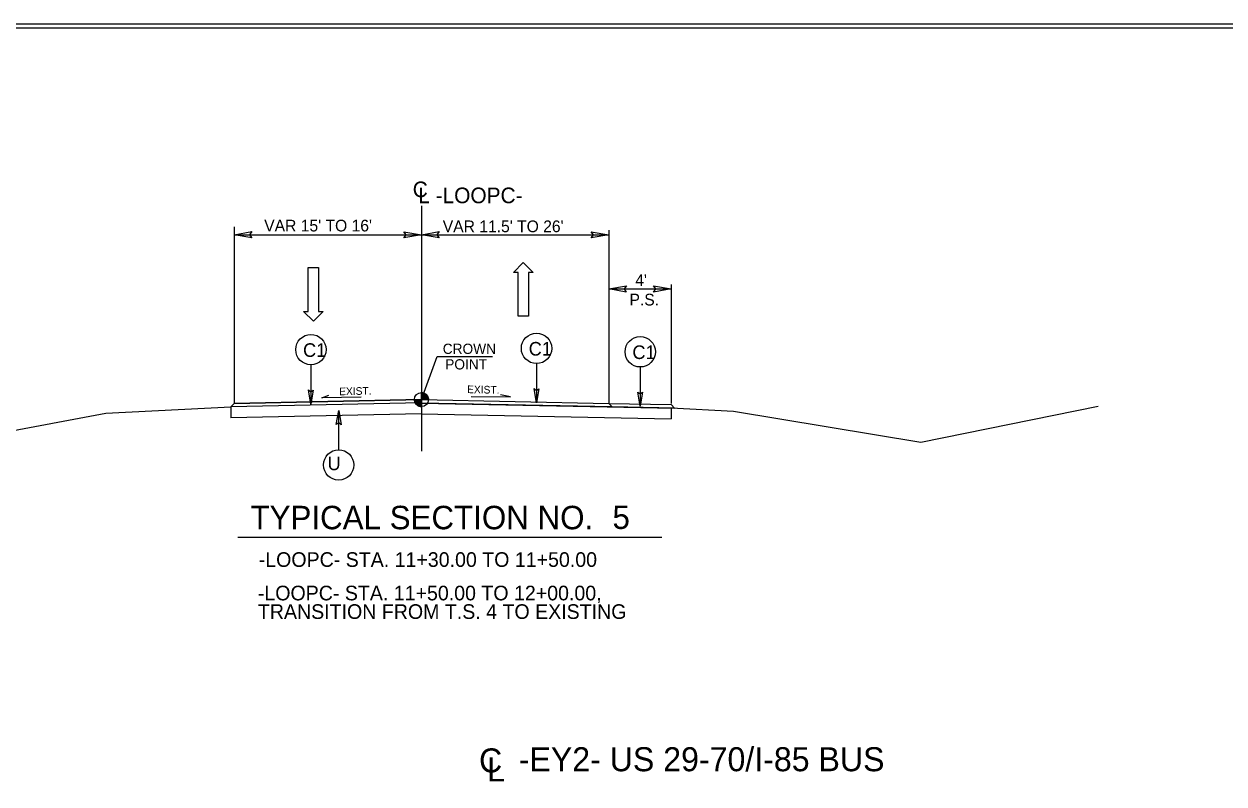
# Model space of a CAD drawing. Extents: x 981824 to 982276, y 44828 to 45204.
# Drawn here: x 982136.8 to 982198.3, y 44961.3 to 45000.2 of the extents above; entities that cross this region are included whole.
import ezdxf

# ---------------------------------------------------------------- set-up
doc = ezdxf.new("R2010")
doc.units = 0
for name, color, linetype in [('Default', 7, 'Continuous'), ('Old_Level_1', 7, 'Continuous'), ('Old_Level_11', 7, 'Continuous'), ('Old_Level_18', 7, 'Continuous'), ('Old_Level_2', 7, 'Continuous'), ('Old_Level_20', 7, 'Continuous'), ('Old_Level_21', 7, 'Continuous'), ('Old_Level_3', 7, 'Continuous'), ('Old_Level_50', 7, 'Continuous'), ('Prop Dimension Text', 7, 'Continuous'), ('Prop Lane Arrow Through CELL', 7, 'Continuous'), ('Prop Roadway Profile Bench Mark Info Text', 7, 'Continuous'), ('Typical Terminator CELL', 7, 'Continuous')]:
    doc.layers.add(name, color=color, linetype=linetype)

msp = doc.modelspace()

# ---------------------------------------------------------------- linework, layer by layer
at = {"layer": 'Default'}
for points in [[(982154.108, 44981.065), (982152.095, 44981.025), (982152.459, 44981.168)], [(982159.749, 44981.104), (982161.759, 44981.078), (982161.259, 44981.18)]]:
    msp.add_lwpolyline(points, dxfattribs=at)
at = {"layer": 'Old_Level_1'}
for p, q in [((982157.202, 44990.865), (982157.202, 44978.304)), ((982147.602, 44989.781), (982147.602, 44980.748)), ((982147.602, 44989.381), (982157.202, 44989.381)), ((982157.202, 44989.381), (982166.802, 44989.381)), ((982166.802, 44989.623), (982166.802, 44980.747)), ((982170.002, 44986.83), (982170.002, 44980.747)), ((982166.802, 44986.605), (982170.002, 44986.605)), ((982157.202, 44980.939), (982158.001, 44983.153)), ((982157.202, 44980.939), (982157.202, 44981.299)), ((982141.024, 44980.249), (982147.433, 44980.573)), ((982157.202, 44980.767), (982147.433, 44980.573)), ((982147.433, 44980.573), (982147.435, 44980.013)), ((982147.611, 44980.748), (982147.434, 44980.573)), ((982157.202, 44980.939), (982147.611, 44980.748)), ((982156.842, 44980.939), (982157.202, 44980.939)), ((982157.199, 44980.766), (982170.177, 44980.508)), ((982157.201, 44980.579), (982157.202, 44980.939)), ((982157.202, 44980.939), (982157.201, 44980.579)), ((982157.202, 44980.939), (982166.799, 44980.747)), ((982157.562, 44980.939), (982157.202, 44980.939)), ((982166.799, 44980.747), (982166.975, 44980.572)), ((982166.799, 44980.747), (982170.002, 44980.683)), ((982170.002, 44980.683), (982170.177, 44980.508)), ((982182.798, 44978.755), (982191.888, 44980.611)), ((982131.486, 44978.47), (982141.024, 44980.249)), ((982157.213, 44980.21), (982147.435, 44980.013)), ((982157.187, 44980.209), (982170.002, 44979.953)), ((982170, 44980.511), (982173.198, 44980.351)), ((982170, 44980.511), (982170.002, 44979.953)), ((982173.198, 44980.351), (982182.798, 44978.755))]:
    msp.add_line(p, q, dxfattribs=at)
for points in [[(982157.205, 44981.299), (982157.205, 44981.299), (982157.205, 44980.939)], [(982157.212, 44981.299), (982157.212, 44980.939)], [(982157.219, 44981.298), (982157.219, 44980.939)], [(982157.227, 44981.298), (982157.227, 44980.939)], [(982157.234, 44981.297), (982157.234, 44980.939)], [(982157.241, 44981.297), (982157.241, 44980.939)], [(982157.248, 44981.296), (982157.248, 44980.939)], [(982157.255, 44981.295), (982157.255, 44980.939)], [(982157.263, 44981.294), (982157.263, 44980.939)], [(982157.27, 44981.293), (982157.27, 44980.939)], [(982157.277, 44981.291), (982157.277, 44980.939)], [(982157.284, 44981.289), (982157.284, 44980.939)], [(982157.291, 44981.288), (982157.291, 44980.939)], [(982157.299, 44981.285), (982157.299, 44980.939)], [(982157.306, 44981.284), (982157.306, 44980.939)], [(982157.313, 44981.281), (982157.313, 44980.939)], [(982157.32, 44981.279), (982157.32, 44980.939)], [(982157.327, 44981.277), (982157.327, 44980.939)], [(982157.335, 44981.273), (982157.335, 44980.939)], [(982157.342, 44981.27), (982157.342, 44980.939)], [(982157.349, 44981.267), (982157.349, 44980.939)], [(982157.356, 44981.264), (982157.356, 44980.939)], [(982157.363, 44981.261), (982157.363, 44980.939)], [(982157.371, 44981.257), (982157.371, 44980.939)], [(982157.378, 44981.253), (982157.378, 44980.939)], [(982157.385, 44981.249), (982157.385, 44980.939)], [(982157.392, 44981.245), (982157.392, 44980.939)], [(982157.399, 44981.24), (982157.399, 44980.939)], [(982157.407, 44981.235), (982157.407, 44980.939)], [(982157.414, 44981.229), (982157.414, 44980.939)], [(982157.421, 44981.225), (982157.421, 44980.939)], [(982157.428, 44981.219), (982157.428, 44980.939)], [(982157.435, 44981.213), (982157.435, 44980.939)], [(982157.443, 44981.206), (982157.443, 44980.939)], [(982157.45, 44981.2), (982157.45, 44980.939)], [(982157.457, 44981.193), (982157.457, 44980.939)], [(982157.464, 44981.185), (982157.464, 44980.939)], [(982157.471, 44981.177), (982157.471, 44980.939)], [(982157.479, 44981.169), (982157.479, 44980.939)], [(982157.486, 44981.16), (982157.486, 44980.939)], [(982157.493, 44981.15), (982157.493, 44980.939)], [(982156.843, 44980.939), (982156.843, 44980.9)], [(982156.851, 44980.939), (982156.851, 44980.857)], [(982156.858, 44980.939), (982156.858, 44980.832)], [(982156.865, 44980.939), (982156.865, 44980.81)], [(982156.872, 44980.939), (982156.872, 44980.793)], [(982156.879, 44980.939), (982156.879, 44980.778)], [(982156.887, 44980.939), (982156.887, 44980.765)], [(982156.894, 44980.939), (982156.894, 44980.752)], [(982156.901, 44980.939), (982156.901, 44980.741)], [(982156.908, 44980.939), (982156.908, 44980.73)], [(982156.915, 44980.939), (982156.915, 44980.721)], [(982156.923, 44980.939), (982156.923, 44980.712)], [(982156.93, 44980.939), (982156.93, 44980.703)], [(982156.937, 44980.939), (982156.937, 44980.695)], [(982156.944, 44980.939), (982156.944, 44980.687)], [(982156.951, 44980.939), (982156.951, 44980.68)], [(982156.959, 44980.939), (982156.959, 44980.673)], [(982156.966, 44980.939), (982156.966, 44980.667)], [(982156.973, 44980.939), (982156.973, 44980.661)], [(982156.98, 44980.939), (982156.98, 44980.655)], [(982156.987, 44980.939), (982156.987, 44980.649)], [(982156.995, 44980.939), (982156.995, 44980.645)], [(982157.002, 44980.939), (982157.002, 44980.64)], [(982157.009, 44980.939), (982157.009, 44980.635)], [(982157.016, 44980.939), (982157.016, 44980.63)], [(982157.023, 44980.939), (982157.023, 44980.626)], [(982157.031, 44980.939), (982157.031, 44980.622)], [(982157.038, 44980.939), (982157.038, 44980.618)], [(982157.045, 44980.939), (982157.045, 44980.615)], [(982157.052, 44980.939), (982157.052, 44980.612)], [(982157.059, 44980.939), (982157.059, 44980.609)], [(982157.067, 44980.939), (982157.067, 44980.605)], [(982157.074, 44980.939), (982157.074, 44980.602)], [(982157.081, 44980.939), (982157.081, 44980.6)], [(982157.088, 44980.939), (982157.088, 44980.597)], [(982157.095, 44980.939), (982157.095, 44980.595)], [(982157.103, 44980.939), (982157.103, 44980.593)], [(982157.11, 44980.939), (982157.11, 44980.591)], [(982157.117, 44980.939), (982157.117, 44980.589)], [(982157.124, 44980.939), (982157.124, 44980.588)], [(982157.131, 44980.939), (982157.131, 44980.586)], [(982157.139, 44980.939), (982157.139, 44980.585)], [(982157.146, 44980.939), (982157.146, 44980.584)], [(982157.153, 44980.939), (982157.153, 44980.582)], [(982157.16, 44980.939), (982157.16, 44980.581)], [(982157.167, 44980.939), (982157.167, 44980.581)], [(982157.175, 44980.939), (982157.175, 44980.58)], [(982157.182, 44980.939), (982157.182, 44980.58)], [(982157.189, 44980.939), (982157.189, 44980.579)], [(982157.196, 44980.939), (982157.196, 44980.579), (982157.196, 44980.579)], [(982157.5, 44981.14), (982157.5, 44980.939)], [(982157.507, 44981.129), (982157.507, 44980.939)], [(982157.515, 44981.117), (982157.515, 44980.939)], [(982157.522, 44981.104), (982157.522, 44980.939)], [(982157.529, 44981.089), (982157.529, 44980.939)], [(982157.536, 44981.072), (982157.536, 44980.939)], [(982157.543, 44981.052), (982157.543, 44980.939)], [(982157.551, 44981.027), (982157.551, 44980.939)], [(982157.558, 44980.99), (982157.558, 44980.939)]]:
    msp.add_lwpolyline(points, dxfattribs=at)
msp.add_circle((982157.201, 44980.939), 0.36, dxfattribs=at)
for start, end in [(359.99048, 89.99048), (179.99048, 269.99048)]:
    msp.add_arc((982157.201, 44980.939), 0.36, start, end, dxfattribs=at)
at = {"layer": 'Old_Level_11'}
for points in [[(982151.661, 44981.431), (982151.537, 44980.711), (982151.409, 44981.435), (982151.537, 44981.343)], [(982163.224, 44981.498), (982163.1, 44980.778), (982162.972, 44981.502), (982163.1, 44981.41)], [(982168.539, 44981.323), (982168.415, 44980.603), (982168.287, 44981.327), (982168.415, 44981.235)], [(982152.837, 44979.66), (982152.961, 44980.38), (982153.089, 44979.656), (982152.961, 44979.748)]]:
    msp.add_lwpolyline(points, close=True, dxfattribs=at)
at = {"layer": 'Old_Level_18'}
msp.add_lwpolyline([(982227.72, 44999.969), (982107.72, 44999.969), (982107.72, 44915.969), (982227.72, 44915.969)], close=True, dxfattribs=at)
at = {"layer": 'Old_Level_21'}
for points in [[(982157.202, 44980.767), (982147.433, 44980.573), (982147.611, 44980.748), (982157.202, 44980.939)], [(982157.202, 44980.939), (982166.799, 44980.747), (982166.975, 44980.572), (982157.199, 44980.766)], [(982166.799, 44980.747), (982170.002, 44980.683), (982170.177, 44980.508), (982166.975, 44980.572)]]:
    msp.add_lwpolyline(points, close=True, dxfattribs=at)
at = {"layer": 'Old_Level_3'}
msp.add_line((982158.001, 44983.153), (982160.847, 44983.153), dxfattribs=at)
at = {"layer": 'Old_Level_50'}
msp.add_lwpolyline([(982228.72, 45000.173), (982095.4, 45000.173), (982095.4, 44915.765), (982228.72, 44915.765)], close=True, dxfattribs=at)
at = {"layer": 'Prop Dimension Text'}
for p, q in [((982151.537, 44982.721), (982151.537, 44980.711)), ((982163.1, 44982.788), (982163.1, 44980.778)), ((982168.415, 44982.612), (982168.415, 44980.603)), ((982152.961, 44978.37), (982152.961, 44980.38))]:
    msp.add_line(p, q, dxfattribs=at)
for centre in [(982151.537, 44983.498), (982163.1, 44983.565), (982168.415, 44983.389), (982152.96, 44977.593)]:
    msp.add_circle(centre, 0.778, dxfattribs=at)
at = {"layer": 'Prop Lane Arrow Through CELL'}
for p, q in [((982161.922, 44987.453), (982162.418, 44987.957)), ((982162.418, 44987.957), (982162.93, 44987.453)), ((982151.399, 44985.458), (982151.399, 44987.698)), ((982151.399, 44987.698), (982151.927, 44987.698)), ((982151.927, 44987.698), (982151.927, 44985.458)), ((982162.162, 44987.453), (982161.922, 44987.453)), ((982162.162, 44985.213), (982162.162, 44987.453)), ((982162.93, 44987.453), (982162.69, 44987.453)), ((982162.69, 44987.453), (982162.69, 44985.213)), ((982151.671, 44984.954), (982151.159, 44985.458)), ((982151.159, 44985.458), (982151.399, 44985.458)), ((982152.167, 44985.458), (982151.671, 44984.954)), ((982151.927, 44985.458), (982152.167, 44985.458)), ((982162.69, 44985.213), (982162.162, 44985.213))]:
    msp.add_line(p, q, dxfattribs=at)
at = {"layer": 'Prop Roadway Profile Bench Mark Info Text'}
msp.add_line((982147.796, 44973.898), (982169.516, 44973.898), dxfattribs=at)
at = {"layer": 'Typical Terminator CELL'}
for points in [[(982148.502, 44989.226), (982147.602, 44989.381), (982148.507, 44989.541), (982148.392, 44989.381)], [(982156.302, 44989.536), (982157.202, 44989.381), (982156.297, 44989.221), (982156.412, 44989.381)], [(982158.102, 44989.226), (982157.202, 44989.381), (982158.107, 44989.541), (982157.992, 44989.381)], [(982165.902, 44989.536), (982166.802, 44989.381), (982165.897, 44989.221), (982166.012, 44989.381)], [(982167.702, 44986.45), (982166.802, 44986.605), (982167.707, 44986.765), (982167.592, 44986.605)], [(982169.102, 44986.76), (982170.002, 44986.605), (982169.097, 44986.445), (982169.212, 44986.605)]]:
    msp.add_lwpolyline(points, close=True, dxfattribs=at)

# ---------------------------------------------------------------- texts
at = {"layer": 'Old_Level_1'}
for s, height, p in [('C', 0.8, (982156.754, 44991.307)), ('L -LOOPC- ', 0.8, (982157.035, 44990.998)), ("VAR 15' TO 16'", 0.6, (982149.143, 44989.551)), ("VAR 11.5' TO 26'", 0.6, (982158.294, 44989.513)), ("4'", 0.6, (982168.16, 44986.758)), ('P.S.', 0.6, (982167.864, 44985.76))]:
    msp.add_text(s, height=height, dxfattribs=at).set_placement(p)
for s, height, p in [('C', 1.23, (982160.153, 44961.849)), ('-EY2- US 29-70/I-85 BUS', 1.23031, (982162.189, 44961.909)), ('L', 1.23, (982160.568, 44961.384))]:
    msp.add_text(s, height=height, rotation=360, dxfattribs=at).set_placement(p)
at = {"layer": 'Old_Level_2'}
for rotation, p in [(1.18742, (982152.988, 44981.162)), (358.81258, (982159.538, 44981.273))]:
    msp.add_text('EXIST.', height=0.392, rotation=rotation, dxfattribs=at).set_placement(p)
at = {"layer": 'Old_Level_20'}
for s, p in [('C1', (982151.135, 44983.128)), ('C1', (982162.699, 44983.195)), ('C1', (982168.013, 44983.019)), ('U ', (982152.39, 44977.326))]:
    msp.add_text(s, height=0.696, dxfattribs=at).set_placement(p)
at = {"layer": 'Old_Level_3'}
for s, p in [('TYPICAL SECTION NO.  ', (982148.44, 44974.301)), ('5', (982166.992, 44974.317))]:
    msp.add_text(s, height=1.2, dxfattribs=at).set_placement(p)
at = {"layer": 'Prop Dimension Text'}
for s, height, p in [('CROWN', 0.5248, (982158.294, 44983.279)), ('POINT', 0.5248, (982158.42, 44982.484)), (' -LOOPC- STA. 11+30.00 TO 11+50.00 ', 0.75, (982148.584, 44972.374)), (' -LOOPC- STA. 11+50.00 TO 12+00.00, ', 0.75, (982148.54, 44970.66)), (' TRANSITION FROM T.S. 4 TO EXISTING', 0.75, (982148.54, 44969.71))]:
    msp.add_text(s, height=height, dxfattribs=at).set_placement(p)

doc.saveas('drawing.dxf')
